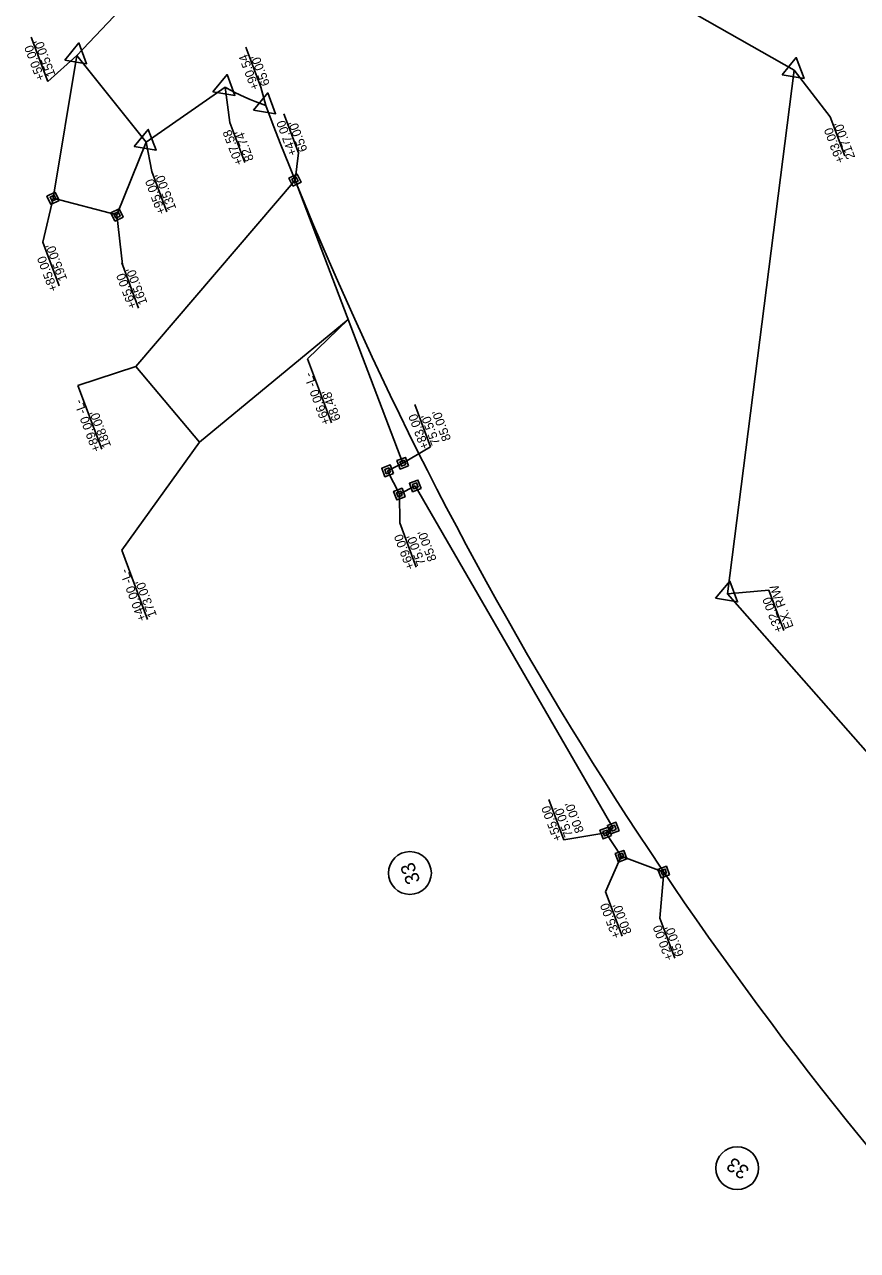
# Model space of a CAD drawing. Extents: x 474184 to 481900, y 489262 to 505659.
# Drawn here: x 478343 to 478811, y 494076 to 494764 of the extents above; entities that cross this region are included whole.
import ezdxf

# ---------------------------------------------------------------- set-up
doc = ezdxf.new("R2010")
doc.units = 0
for name, color, linetype in [('Prop Drainage Structure Drop Inlet Grate 2 Wide Slots and Sag Grates 840 22 CELL', 7, 'Continuous'), ('Prop Drainage Structure Outlet Berm Ditch 850 10 Label', 7, 'Continuous'), ('Prop Drainage Structure Pipe CSP 15in', 7, 'Continuous'), ('Prop Drainage Structure Pipe RCP 18in Class IV', 7, 'Continuous'), ('Prop Drainage Structure Pipe RCP 18in Class IV Label', 7, 'Continuous'), ('Prop Drainage Structure Pipe Side Drain 15in Label', 7, 'Continuous'), ('Prop Drainage Structure Pipe Stub Out CELL', 7, 'Continuous'), ('Prop Drainage Structure Plot Symbol 50 Scale', 7, 'Continuous'), ('Prop Earthen Structure Base Ditch Lateral Detail Label', 7, 'Continuous'), ('Prop Earthen Structure False Sump CELL', 7, 'Continuous'), ('Prop Earthen Structure False Sump Label', 7, 'Continuous')]:
    doc.layers.add(name, color=color, linetype=linetype)

msp = doc.modelspace()

# ---------------------------------------------------------------- linework, layer by layer
at = {"layer": 'Prop Drainage Structure Drop Inlet Grate 2 Wide Slots and Sag Grates 840 22 CELL'}
for p, q in [((478359.41, 494666.09), (478372.69, 494746.09)), ((478411.61, 494697.58), (478395.27, 494656.72)), ((478395.27, 494656.72), (478359.41, 494666.09))]:
    msp.add_line(p, q, dxfattribs=at)
at = {"layer": 'Prop Drainage Structure Outlet Berm Ditch 850 10 Label'}
for p, q in [((478555.62, 494517.51), (478495.16, 494676.29)), ((478555.62, 494517.51), (478547.13, 494513.24)), ((478553.72, 494500.24), (478547.13, 494513.24)), ((478562.63, 494504.79), (478553.72, 494500.24)), ((478673.7, 494312.88), (478562.63, 494504.79)), ((478673.7, 494312.88), (478669.51, 494310.16)), ((478678.05, 494297.13), (478669.51, 494310.16)), ((478702.03, 494288.24), (478678.05, 494297.13))]:
    msp.add_line(p, q, dxfattribs=at)
at = {"layer": 'Prop Drainage Structure Pipe CSP 15in'}
for p, q in [((478559.64, 494287.71), (478559.64, 494287.71)), ((478743.27, 494122.15), (478743.27, 494122.15))]:
    msp.add_line(p, q, dxfattribs=at)
for centre in [(478559.64, 494287.71), (478743.27, 494122.15)]:
    msp.add_circle(centre, 12, dxfattribs=at)
at = {"layer": 'Prop Drainage Structure Pipe RCP 18in Class IV'}
for p, q in [((478372.69, 494746.09), (478372.69, 494746.09)), ((478775.2, 494737.87), (478775.2, 494737.87)), ((478455.88, 494728.35), (478455.88, 494728.35)), ((478478.7, 494718.09), (478478.7, 494718.09)), ((478411.61, 494697.58), (478411.61, 494697.58)), ((478495.16, 494676.29), (478495.16, 494676.29)), ((478359.41, 494666.09), (478359.41, 494666.09)), ((478395.27, 494656.72), (478395.27, 494656.72)), ((478547.13, 494513.24), (478547.13, 494513.24)), ((478555.62, 494517.51), (478555.62, 494517.51)), ((478553.72, 494500.24), (478553.72, 494500.24)), ((478562.63, 494504.79), (478562.63, 494504.79)), ((478737.89, 494444.3), (478737.89, 494444.3)), ((478669.51, 494310.16), (478669.51, 494310.16)), ((478673.7, 494312.88), (478673.7, 494312.88)), ((478678.05, 494297.13), (478678.05, 494297.13)), ((478702.03, 494288.24), (478702.03, 494288.24))]:
    msp.add_line(p, q, dxfattribs=at)
for points in [[(478365.93, 494743.58), (478373.89, 494753.19), (478378.25, 494741.5)], [(478768.43, 494735.36), (478776.4, 494744.97), (478780.76, 494733.28)], [(478449.11, 494725.84), (478457.08, 494735.45), (478461.44, 494723.76)], [(478471.94, 494715.58), (478479.9, 494725.19), (478484.27, 494713.5)], [(478404.85, 494695.07), (478412.81, 494704.68), (478417.17, 494692.99)], [(478731.12, 494441.79), (478739.09, 494451.4), (478743.45, 494439.71)]]:
    msp.add_lwpolyline(points, close=True, dxfattribs=at)
at = {"layer": 'Prop Drainage Structure Pipe RCP 18in Class IV Label'}
for points in [[(478493.99, 494672.88), (478491.75, 494677.46), (478496.33, 494679.69), (478498.56, 494675.11)], [(478494.57, 494674.58), (478493.46, 494676.87), (478495.74, 494677.99), (478496.86, 494675.7)], [(478358.24, 494662.68), (478356.01, 494667.26), (478360.58, 494669.49), (478362.81, 494664.92)], [(478358.82, 494664.39), (478357.71, 494666.67), (478360, 494667.79), (478361.11, 494665.5)], [(478394.09, 494653.32), (478391.86, 494657.9), (478396.44, 494660.13), (478398.67, 494655.55)], [(478394.68, 494655.02), (478393.56, 494657.31), (478395.85, 494658.42), (478396.97, 494656.14)], [(478558.9, 494516.02), (478554.13, 494514.23), (478552.35, 494519), (478557.11, 494520.78)], [(478550.41, 494511.75), (478545.64, 494509.97), (478543.86, 494514.74), (478548.63, 494516.52)], [(478548.77, 494512.5), (478546.39, 494511.61), (478545.5, 494513.99), (478547.88, 494514.88)], [(478557.26, 494516.76), (478554.87, 494515.87), (478553.98, 494518.26), (478556.37, 494519.15)], [(478565.9, 494503.3), (478561.13, 494501.51), (478559.35, 494506.28), (478564.12, 494508.06)], [(478564.27, 494504.04), (478561.88, 494503.15), (478560.99, 494505.54), (478563.37, 494506.43)], [(478557, 494498.74), (478552.23, 494496.96), (478550.45, 494501.73), (478555.22, 494503.51)], [(478555.36, 494499.49), (478552.98, 494498.6), (478552.09, 494500.99), (478554.47, 494501.88)], [(478676.97, 494311.39), (478672.2, 494309.61), (478670.42, 494314.38), (478675.19, 494316.16)], [(478675.33, 494312.14), (478672.95, 494311.25), (478672.06, 494313.63), (478674.44, 494314.52)], [(478672.78, 494308.66), (478668.01, 494306.88), (478666.23, 494311.65), (478671, 494313.43)], [(478671.14, 494309.41), (478668.76, 494308.52), (478667.87, 494310.9), (478670.25, 494311.8)], [(478681.33, 494295.63), (478676.56, 494293.85), (478674.78, 494298.62), (478679.55, 494300.4)], [(478679.69, 494296.38), (478677.31, 494295.49), (478676.42, 494297.87), (478678.8, 494298.76)], [(478705.3, 494286.75), (478700.54, 494284.97), (478698.76, 494289.74), (478703.52, 494291.52)], [(478703.67, 494287.49), (478701.28, 494286.6), (478700.39, 494288.99), (478702.78, 494289.88)]]:
    msp.add_lwpolyline(points, close=True, dxfattribs=at)
at = {"layer": 'Prop Drainage Structure Pipe Side Drain 15in Label'}
for p, q in [((478775.2, 494737.87), (478565.24, 494857.34)), ((478411.61, 494697.58), (478372.69, 494746.09)), ((478737.89, 494444.3), (478775.2, 494737.87)), ((478455.88, 494728.35), (478411.61, 494697.58))]:
    msp.add_line(p, q, dxfattribs=at)
for points in [[(478372.69, 494746.09), (478400.39, 494775.31)], [(479028, 494114.97), (478737.89, 494444.3)]]:
    msp.add_lwpolyline(points, dxfattribs=at)
for centre, radius, start, end in [((478530.36, 494863.49), 154.3, 241.1376, 250.44111), ((480454.83, 495471.85), 2115, 200.87848, 221.29659)]:
    msp.add_arc(centre, radius, start, end, dxfattribs=at)
at = {"layer": 'Prop Drainage Structure Pipe Stub Out CELL'}
for p, q in [((478405.84, 494571.7), (478495.16, 494676.29)), ((478524.95, 494598.06), (478441.52, 494529.34)), ((478441.52, 494529.34), (478405.84, 494571.7))]:
    msp.add_line(p, q, dxfattribs=at)
at = {"layer": 'Prop Drainage Structure Plot Symbol 50 Scale'}
for p, q in [((478347.22, 494756.35), (478356.46, 494731.6)), ((478467.58, 494750.92), (478475.99, 494728.39)), ((478356.46, 494731.6), (478372.69, 494746.09)), ((478795.38, 494711.67), (478775.2, 494737.87)), ((478458.57, 494708.61), (478455.88, 494728.35)), ((478478.7, 494718.09), (478475.99, 494728.39)), ((478458.57, 494708.61), (478466.98, 494686.08)), ((478795.38, 494711.67), (478803.54, 494689.8)), ((478414.9, 494681.04), (478411.61, 494697.58)), ((478414.9, 494681.04), (478423.31, 494658.51)), ((478760.93, 494446.27), (478769.34, 494423.74))]:
    msp.add_line(p, q, dxfattribs=at)
msp.add_lwpolyline([(478760.93, 494446.27), (478737.89, 494444.3)], dxfattribs=at)
at = {"layer": 'Prop Earthen Structure Base Ditch Lateral Detail Label'}
for p, q in [((478497.05, 494691.63), (478488.94, 494713.36)), ((478495.16, 494676.29), (478497.05, 494691.63)), ((478562.33, 494550.45), (478571.21, 494526.65)), ((478553.93, 494484.02), (478563.19, 494459.22)), ((478637.51, 494328.86), (478645.92, 494306.33)), ((478669.42, 494277.25), (478678.72, 494252.35)), ((478699.81, 494262.48), (478708.22, 494239.95))]:
    msp.add_line(p, q, dxfattribs=at)
for points in [[(478571.21, 494526.65), (478555.62, 494517.51)], [(478553.93, 494484.02), (478553.72, 494500.24)], [(478645.92, 494306.33), (478669.51, 494310.16)], [(478669.42, 494277.25), (478678.05, 494297.13)], [(478699.81, 494262.48), (478702.03, 494288.24)]]:
    msp.add_lwpolyline(points, dxfattribs=at)
at = {"layer": 'Prop Earthen Structure False Sump CELL'}
for p, q in [((478353.64, 494641.41), (478359.41, 494666.09)), ((478398.29, 494628.93), (478395.27, 494656.72)), ((478353.64, 494641.41), (478362.76, 494616.98)), ((478397.92, 494629.92), (478407.43, 494604.43))]:
    msp.add_line(p, q, dxfattribs=at)
at = {"layer": 'Prop Earthen Structure False Sump Label'}
for p, q in [((478502.21, 494576.02), (478515.62, 494540.11)), ((478373.4, 494561.13), (478386.72, 494525.46)), ((478397.96, 494468.84), (478412.48, 494429.95))]:
    msp.add_line(p, q, dxfattribs=at)
for points in [[(478502.21, 494576.02), (478524.95, 494598.06)], [(478373.4, 494561.13), (478405.84, 494571.7)], [(478397.96, 494468.84), (478441.52, 494529.34)]]:
    msp.add_lwpolyline(points, dxfattribs=at)

# ---------------------------------------------------------------- texts
at = {"layer": 'Prop Drainage Structure Pipe CSP 15in'}
for rotation, p in [(110.46898, (478565.59, 494283.23)), (145.2516, (478750.66, 494121.9))]:
    msp.add_text('33', height=8, rotation=rotation, dxfattribs=at).set_placement(p)
at = {"layer": 'Prop Drainage Structure Plot Symbol 50 Scale'}
for s, p in [("155.00'", (478360.86, 494735.33)), ('+50.00', (478355, 494733.14)), ('+90.54', (478475.32, 494727.96)), ("65.00'", (478481.17, 494730.14)), ("217.00'", (478809.51, 494689.06)), ('+07.58', (478466.3, 494685.65)), ("82.74'", (478472.15, 494687.84)), ('+93.00', (478803.65, 494686.87)), ("135.00'", (478428.66, 494660.33)), ('+95.00', (478422.8, 494658.14)), ('EX. R/W', (478774.96, 494425.84)), ('+32.00', (478769.1, 494423.65))]:
    msp.add_text(s, height=5, rotation=110.46898, dxfattribs=at).set_placement(p)
at = {"layer": 'Prop Earthen Structure Base Ditch Lateral Detail Label'}
for s, p in [('+47.00', (478496.42, 494690.98)), ("65.00'", (478502.27, 494693.16)), ('+83.00', (478570.5, 494526.39)), ("75.50'", (478576.65, 494528.68)), ("85.00'", (478582.79, 494530.97)), ("85.00'", (478574.71, 494463.51)), ('+69.00', (478562.42, 494458.93)), ("75.00'", (478568.56, 494461.22)), ('+55.00', (478645.06, 494306.64)), ("75.00'", (478651.21, 494308.93)), ("80.00'", (478657.35, 494311.22)), ('+35.00', (478678.01, 494252.08)), ("80.00'", (478684.15, 494254.38)), ('+20.00', (478707.64, 494239.74)), ("65.00'", (478713.49, 494241.92))]:
    msp.add_text(s, height=5, rotation=110.46898, dxfattribs=at).set_placement(p)
at = {"layer": 'Prop Earthen Structure False Sump CELL'}
for s, p in [("195.00'", (478367.43, 494620.79)), ('+85.00 ', (478362.18, 494614.87)), ('+65.00 ', (478406.58, 494605.22)), ("165.00'", (478412.43, 494607.4))]:
    msp.add_text(s, height=5, rotation=110.46898, dxfattribs=at).set_placement(p)
at = {"layer": 'Prop Earthen Structure False Sump Label'}
for s, p in [('+66.00 -L-', (478515.1, 494540.11)), ("68.48'", (478520.95, 494542.29)), ('+89.00 -L-', (478386.22, 494525.01)), ("188.00'", (478392.08, 494527.19)), ('+40.00 -L-', (478411.87, 494429.94)), ("173.00'", (478417.73, 494432.13))]:
    msp.add_text(s, height=5, rotation=110.46898, dxfattribs=at).set_placement(p)

doc.saveas('drawing.dxf')
